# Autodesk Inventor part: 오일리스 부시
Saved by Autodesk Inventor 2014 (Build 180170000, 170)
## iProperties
Created: 2024-05
Part Number: 오일리스 부시
Material: 일반
Document SubType Name: Modeling
Designer: dg
Density: 1 g/cm^3
Appearance: 기본값
Author: dg
Author: jhkim
Creation Date: 2024-05-07
Sending System: Autodesk Inventor 2025
Preprocessor: ST-DEVELOPER v20
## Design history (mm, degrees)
node "오일리스 부시1"
node "솔리드1"
node "기준1"
